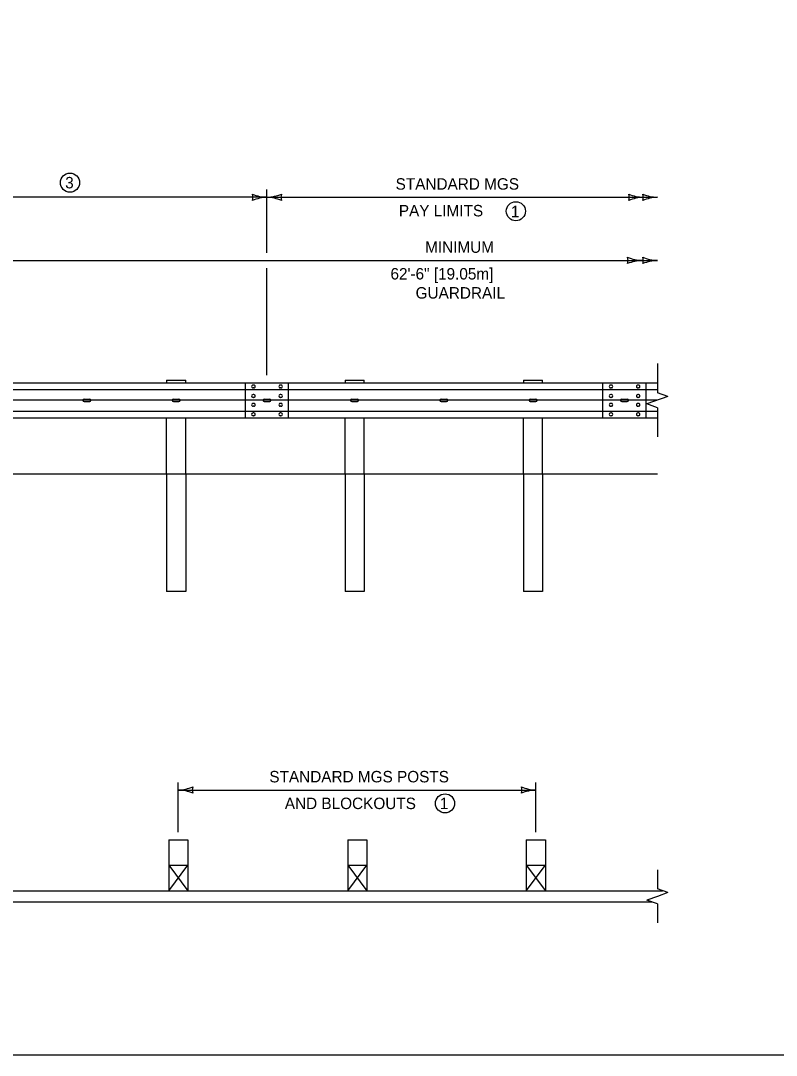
# Model space of a CAD drawing. Extents: x 49991.4 to 50021, y 49987.6 to 50011.4.
# Drawn here: x 50007.16 to 50011.12, y 49987.8 to 49993.22 of the extents above; entities that cross this region are included whole.
import ezdxf

# ---------------------------------------------------------------- set-up
doc = ezdxf.new("R2010")
doc.units = 0
for name, color, linetype in [('Level 1', 7, 'Continuous'), ('Level 2', 7, 'Continuous'), ('Level 3', 7, 'Continuous'), ('Level 4', 7, 'Continuous'), ('Level 5', 7, 'Continuous'), ('Level 6', 7, 'Continuous')]:
    doc.layers.add(name, color=color, linetype=linetype)

msp = doc.modelspace()

# ---------------------------------------------------------------- linework, layer by layer
at = {"layer": 'Level 1'}
for p, q in [((50007.9289, 49991.3366), (50007.9289, 49991.3233)), ((50007.9289, 49991.3366), (50008.0288, 49991.3366)), ((50008.0288, 49991.3233), (50008.0288, 49991.3366)), ((50008.8633, 49991.3366), (50008.8633, 49991.3233)), ((50008.8633, 49991.3366), (50008.9633, 49991.3366)), ((50008.9633, 49991.3233), (50008.9633, 49991.3366)), ((50009.7977, 49991.3366), (50009.7977, 49991.3233)), ((50009.7977, 49991.3366), (50009.8977, 49991.3366)), ((50009.8977, 49991.3233), (50009.8977, 49991.3366)), ((50000.0289, 49991.3233), (50010.4985, 49991.3233)), ((50000.0289, 49991.2873), (50010.4985, 49991.2873)), ((50008.3411, 49991.138), (50008.3411, 49991.3226)), ((50008.3852, 49991.311), (50008.3816, 49991.311)), ((50008.3852, 49991.2959), (50008.3816, 49991.2959)), ((50008.5275, 49991.311), (50008.5239, 49991.311)), ((50008.5275, 49991.2959), (50008.5239, 49991.2959)), ((50010.2135, 49991.138), (50010.2135, 49991.3226)), ((50010.2577, 49991.311), (50010.2541, 49991.311)), ((50010.2577, 49991.2959), (50010.2541, 49991.2959)), ((50010.3999, 49991.311), (50010.3963, 49991.311)), ((50010.3999, 49991.2959), (50010.3963, 49991.2959)), ((50007.497, 49991.2373), (50007.5262, 49991.2373)), ((50007.497, 49991.2248), (50007.5262, 49991.2248)), ((50007.9642, 49991.2373), (50007.9934, 49991.2373)), ((50007.9642, 49991.2248), (50007.9934, 49991.2248)), ((50008.3852, 49991.2611), (50008.3816, 49991.2611)), ((50008.3852, 49991.246), (50008.3816, 49991.246)), ((50008.4397, 49991.2373), (50008.4689, 49991.2373)), ((50008.4397, 49991.2248), (50008.4689, 49991.2248)), ((50008.5275, 49991.2611), (50008.5239, 49991.2611)), ((50008.5275, 49991.246), (50008.5239, 49991.246)), ((50008.8987, 49991.2373), (50008.9279, 49991.2373)), ((50008.8987, 49991.2248), (50008.9279, 49991.2248)), ((50009.3659, 49991.2373), (50009.3951, 49991.2373)), ((50009.3659, 49991.2248), (50009.3951, 49991.2248)), ((50009.8331, 49991.2373), (50009.8623, 49991.2373)), ((50009.8331, 49991.2248), (50009.8623, 49991.2248)), ((50010.2577, 49991.2611), (50010.2541, 49991.2611)), ((50010.2577, 49991.246), (50010.2541, 49991.246)), ((50010.3122, 49991.2373), (50010.3413, 49991.2373)), ((50010.3122, 49991.2248), (50010.3413, 49991.2248)), ((50010.3999, 49991.2611), (50010.3963, 49991.2611)), ((50010.3999, 49991.246), (50010.3963, 49991.246)), ((50000.0289, 49991.1748), (50010.4985, 49991.1748)), ((50008.3852, 49991.2146), (50008.3816, 49991.2146)), ((50008.3852, 49991.1995), (50008.3816, 49991.1995)), ((50008.5275, 49991.2146), (50008.5239, 49991.2146)), ((50008.5275, 49991.1995), (50008.5239, 49991.1995)), ((50010.2577, 49991.2146), (50010.2541, 49991.2146)), ((50010.2577, 49991.1995), (50010.2541, 49991.1995)), ((50010.3999, 49991.2146), (50010.3963, 49991.2146)), ((50010.3999, 49991.1995), (50010.3963, 49991.1995)), ((50000.0289, 49991.1388), (50010.4985, 49991.1388)), ((50007.9289, 49990.8443), (50007.9289, 49991.1388)), ((50008.0288, 49990.8443), (50008.0288, 49991.1388)), ((50008.3852, 49991.1647), (50008.3816, 49991.1647)), ((50008.3852, 49991.1496), (50008.3816, 49991.1496)), ((50008.5275, 49991.1647), (50008.5239, 49991.1647)), ((50008.5275, 49991.1496), (50008.5239, 49991.1496)), ((50008.8633, 49990.8443), (50008.8633, 49991.1388)), ((50008.9632, 49990.8443), (50008.9632, 49991.1388)), ((50009.7977, 49990.8443), (50009.7977, 49991.1388)), ((50009.8976, 49990.8443), (50009.8976, 49991.1388)), ((50010.2577, 49991.1647), (50010.2541, 49991.1647)), ((50010.2577, 49991.1496), (50010.2541, 49991.1496)), ((50010.3999, 49991.1647), (50010.3963, 49991.1647)), ((50010.3999, 49991.1496), (50010.3963, 49991.1496)), ((50010.4985, 49990.8443), (50000.0289, 49990.8443)), ((50007.9399, 49988.9278), (50008.0399, 49988.9278)), ((50007.9399, 49988.9278), (50007.9399, 49988.6612)), ((50008.0399, 49988.9278), (50008.0399, 49988.6612)), ((50008.8779, 49988.9278), (50008.9779, 49988.9278)), ((50008.8779, 49988.9278), (50008.8779, 49988.6612)), ((50008.9779, 49988.9278), (50008.9779, 49988.6612)), ((50009.8124, 49988.9278), (50009.9124, 49988.9278)), ((50009.8124, 49988.9278), (50009.8124, 49988.6612)), ((50009.9124, 49988.9278), (50009.9124, 49988.6612)), ((50007.9399, 49988.7945), (50008.0399, 49988.7945)), ((50007.9399, 49988.7945), (50008.0399, 49988.6612)), ((50007.9399, 49988.6612), (50008.0399, 49988.7945)), ((50008.8779, 49988.7945), (50008.9779, 49988.7945)), ((50008.8779, 49988.7945), (50008.9779, 49988.6612)), ((50008.8779, 49988.6612), (50008.9779, 49988.7945)), ((50009.8124, 49988.7945), (50009.9124, 49988.7945)), ((50009.8124, 49988.7945), (50009.9124, 49988.6612)), ((50009.8124, 49988.6612), (50009.9124, 49988.7945)), ((50004.8055, 49988.6612), (50010.525, 49988.6612)), ((50004.8593, 49988.6026), (50010.4711, 49988.6026))]:
    msp.add_line(p, q, dxfattribs=at)
msp.add_lwpolyline([(49999.3835, 49998.9992), (50016.7501, 49998.9992), (50016.7501, 49987.7988), (49999.3835, 49987.7988)], close=True, dxfattribs=at)
for centre, start, end in [((50007.497, 49991.231), 90, 180), ((50007.497, 49991.231), 180, 270), ((50007.5262, 49991.231), 360, 90), ((50007.5262, 49991.231), 270, 0), ((50007.9642, 49991.231), 90, 180), ((50007.9642, 49991.231), 180, 270), ((50007.9934, 49991.231), 360, 90), ((50007.9934, 49991.231), 270, 0), ((50008.4397, 49991.231), 90, 180), ((50008.4397, 49991.231), 180, 270), ((50008.4689, 49991.231), 360, 90), ((50008.4689, 49991.231), 270, 0), ((50008.8987, 49991.231), 90, 180), ((50008.8987, 49991.231), 180, 270), ((50008.9279, 49991.231), 360, 90), ((50008.9279, 49991.231), 270, 0), ((50009.3659, 49991.231), 90, 180), ((50009.3659, 49991.231), 180, 270), ((50009.3951, 49991.231), 360, 90), ((50009.3951, 49991.231), 270, 0), ((50009.8331, 49991.231), 90, 180), ((50009.8331, 49991.231), 180, 270), ((50009.8623, 49991.231), 360, 90), ((50009.8623, 49991.231), 270, 0), ((50010.3122, 49991.231), 90, 180), ((50010.3122, 49991.231), 180, 270), ((50010.3413, 49991.231), 360, 90), ((50010.3413, 49991.231), 270, 0)]:
    msp.add_arc(centre, 0.00625, start, end, dxfattribs=at)
for centre, start_param, end_param in [((50008.3816, 49991.3035), 1.570796, 4.712389), ((50008.3852, 49991.3035), 4.712389, 7.853982), ((50008.5239, 49991.3035), 1.570796, 4.712389), ((50008.5275, 49991.3035), 4.712389, 7.853982), ((50010.2541, 49991.3035), 1.570796, 4.712389), ((50010.2577, 49991.3035), 4.712389, 7.853982), ((50010.3963, 49991.3035), 1.570796, 4.712389), ((50010.3999, 49991.3035), 4.712389, 7.853982), ((50008.3816, 49991.2536), 1.570796, 4.712389), ((50008.3852, 49991.2536), 4.712389, 7.853982), ((50008.5239, 49991.2536), 1.570796, 4.712389), ((50008.5275, 49991.2536), 4.712389, 7.853982), ((50010.2541, 49991.2536), 1.570796, 4.712389), ((50010.2577, 49991.2536), 4.712389, 7.853982), ((50010.3963, 49991.2536), 1.570796, 4.712389), ((50010.3999, 49991.2536), 4.712389, 7.853982), ((50008.3816, 49991.2071), 1.570796, 4.712389), ((50008.3852, 49991.2071), 4.712389, 7.853982), ((50008.5239, 49991.2071), 1.570796, 4.712389), ((50008.5275, 49991.2071), 4.712389, 7.853982), ((50010.2541, 49991.2071), 1.570796, 4.712389), ((50010.2577, 49991.2071), 4.712389, 7.853982), ((50010.3963, 49991.2071), 1.570796, 4.712389), ((50010.3999, 49991.2071), 4.712389, 7.853982), ((50008.3816, 49991.1572), 1.570796, 4.712389), ((50008.3852, 49991.1572), 4.712389, 7.853982), ((50008.5239, 49991.1572), 1.570796, 4.712389), ((50008.5275, 49991.1572), 4.712389, 7.853982), ((50010.2541, 49991.1572), 1.570796, 4.712389), ((50010.2577, 49991.1572), 4.712389, 7.853982), ((50010.3963, 49991.1572), 1.570796, 4.712389), ((50010.3999, 49991.1572), 4.712389, 7.853982)]:
    msp.add_ellipse(centre, major_axis=(0.00756, 0), ratio=0.998676, start_param=start_param, end_param=end_param, dxfattribs=at)
at = {"layer": 'Level 2'}
for centre in [(50007.4227, 49992.3713), (50009.7577, 49992.2217), (50009.3866, 49989.1187)]:
    msp.add_circle(centre, 0.05, dxfattribs=at)
at = {"layer": 'Level 3'}
for p, q in [((50008.4543, 49992.0038), (50008.4543, 49992.3346)), ((50008.4543, 49992.2946), (50000.0289, 49992.2946)), ((50008.4543, 49992.2946), (50010.4985, 49992.2946)), ((50007.0444, 49991.9638), (50010.4985, 49991.9638)), ((50008.4543, 49991.3633), (50008.4543, 49991.9238)), ((50007.9899, 49988.9678), (50007.9899, 49989.2289)), ((50009.8624, 49988.9678), (50009.8624, 49989.2289)), ((50007.9899, 49989.1889), (50009.8624, 49989.1889))]:
    msp.add_line(p, q, dxfattribs=at)
for centre, radius, start, end in [((50008.4634, 49992.5167), 0.2223, 247.456, 267.6395), ((50008.3261, 49992.2946), 0.0548, 342.1388, 17.8612), ((50008.4428, 49992.5273), 0.233, 272.8273, 292.0772), ((50008.5825, 49992.2946), 0.0548, 162.1388, 197.8612), ((50010.4342, 49992.5167), 0.2223, 247.456, 267.6395), ((50010.2969, 49992.2946), 0.0548, 342.1388, 17.8612), ((50010.5077, 49992.5167), 0.2223, 247.456, 267.6395), ((50010.3703, 49992.2946), 0.0548, 342.1388, 17.8612), ((50008.4658, 49992.0618), 0.233, 92.8273, 112.0772), ((50008.4451, 49992.0724), 0.2223, 67.456, 87.6395), ((50010.4366, 49992.0618), 0.233, 92.8273, 112.0772), ((50010.51, 49992.0618), 0.233, 92.8273, 112.0772), ((50010.2904, 49991.9638), 0.0548, 342.1388, 17.8612), ((50010.4301, 49992.1965), 0.233, 247.9228, 267.1727), ((50010.4278, 49991.7416), 0.2223, 92.3605, 112.544), ((50010.3703, 49991.9638), 0.0548, 342.1388, 17.8612), ((50010.51, 49992.1965), 0.233, 247.9228, 267.1727), ((50010.5077, 49991.7416), 0.2223, 92.3605, 112.544), ((50007.9784, 49989.4216), 0.233, 272.8273, 292.0772), ((50007.9807, 49988.9667), 0.2223, 67.456, 87.6395), ((50008.1181, 49989.1889), 0.0548, 162.1388, 197.8612), ((50009.8715, 49989.411), 0.2223, 247.456, 267.6395), ((50009.7342, 49989.1889), 0.0548, 342.1388, 17.8612), ((50009.8739, 49988.9562), 0.233, 92.8273, 112.0772)]:
    msp.add_arc(centre, radius, start, end, dxfattribs=at)
at = {"layer": 'Level 4'}
for p, q in [((50008.5675, 49991.138), (50008.5675, 49991.3226)), ((50010.44, 49991.138), (50010.44, 49991.3226)), ((50007.9289, 49990.8443), (50007.9289, 49990.229)), ((50008.0288, 49990.8443), (50008.0288, 49990.229)), ((50008.8633, 49990.8443), (50008.8633, 49990.229)), ((50008.9632, 49990.8443), (50008.9632, 49990.229)), ((50009.7977, 49990.8443), (50009.7977, 49990.229)), ((50009.8976, 49990.8443), (50009.8976, 49990.229)), ((50008.0288, 49990.229), (50007.9289, 49990.229)), ((50008.9632, 49990.229), (50008.8633, 49990.229)), ((50009.8976, 49990.229), (50009.7977, 49990.229))]:
    msp.add_line(p, q, dxfattribs=at)
at = {"layer": 'Level 5'}
msp.add_line((50010.4985, 49991.231), (50000.0289, 49991.231), dxfattribs=at)
at = {"layer": 'Level 6'}
for p, q in [((50010.4985, 49991.4232), (50010.4985, 49991.2699)), ((50010.5534, 49991.2505), (50010.4437, 49991.2116)), ((50010.5534, 49991.2505), (50010.4985, 49991.2699)), ((50010.4985, 49991.1921), (50010.4437, 49991.2116)), ((50010.4985, 49991.1921), (50010.4985, 49991.0387)), ((50010.4985, 49988.7706), (50010.4985, 49988.6706)), ((50010.4985, 49988.6317), (50010.4437, 49988.6123)), ((50010.5534, 49988.6512), (50010.4985, 49988.6706)), ((50010.5534, 49988.6512), (50010.4985, 49988.6317)), ((50010.4985, 49988.5928), (50010.4437, 49988.6123)), ((50010.4985, 49988.5928), (50010.4985, 49988.4928))]:
    msp.add_line(p, q, dxfattribs=at)

# ---------------------------------------------------------------- texts
at = {"layer": 'Level 2'}
for s, p in [('3', (50007.3975, 49992.3413)), ('STANDARD MGS', (50009.128, 49992.3346)), ('PAY LIMITS', (50009.1449, 49992.1946)), ('1', (50009.732, 49992.1903)), ('MINIMUM', (50009.2823, 49992.0038)), (' 62\'-6" [19.05m]', (50009.0788, 49991.8638)), ('GUARDRAIL', (50009.2327, 49991.7638)), ('STANDARD MGS POSTS', (50008.4667, 49989.2289)), ('AND BLOCKOUTS', (50008.5477, 49989.0889)), ('1', (50009.3595, 49989.0889))]:
    msp.add_text(s, height=0.06, dxfattribs=at).set_placement(p)

doc.saveas('drawing.dxf')
